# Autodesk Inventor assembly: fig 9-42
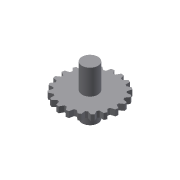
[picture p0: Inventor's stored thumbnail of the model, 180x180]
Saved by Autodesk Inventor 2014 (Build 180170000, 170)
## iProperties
Created: 2013-07
Part Number: fig 9-42
Document SubType Name: Assembly
Designer: CADCIM
Author: CADCIM
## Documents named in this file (3)
- E:\APS\Autodesk Inventor 2014-Project\inventor_2014_partfiles\Inventor_2014_prt\c09_Inv_2014_prt\c09_inv_2014_prt\fig 9-42.iam
- E:\APS\Autodesk Inventor 2014-Project\inventor_2014_partfiles\Inventor_2014_prt\c09_Inv_2014_prt\c09_inv_2014_prt\13.ipt
- E:\APS\Autodesk Inventor 2014-Project\inventor_2014_partfiles\Inventor_2014_prt\c09_Inv_2014_prt\c09_inv_2014_prt\14.ipt
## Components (2 placed, 2 different names)
1. 13:1 — Rotational:1
2. 14:1 — Rotational:1
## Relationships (1: RevoluteJoint 1)
- Rotational:1 [RevoluteJoint]: 13:1 ↔ 14:1
